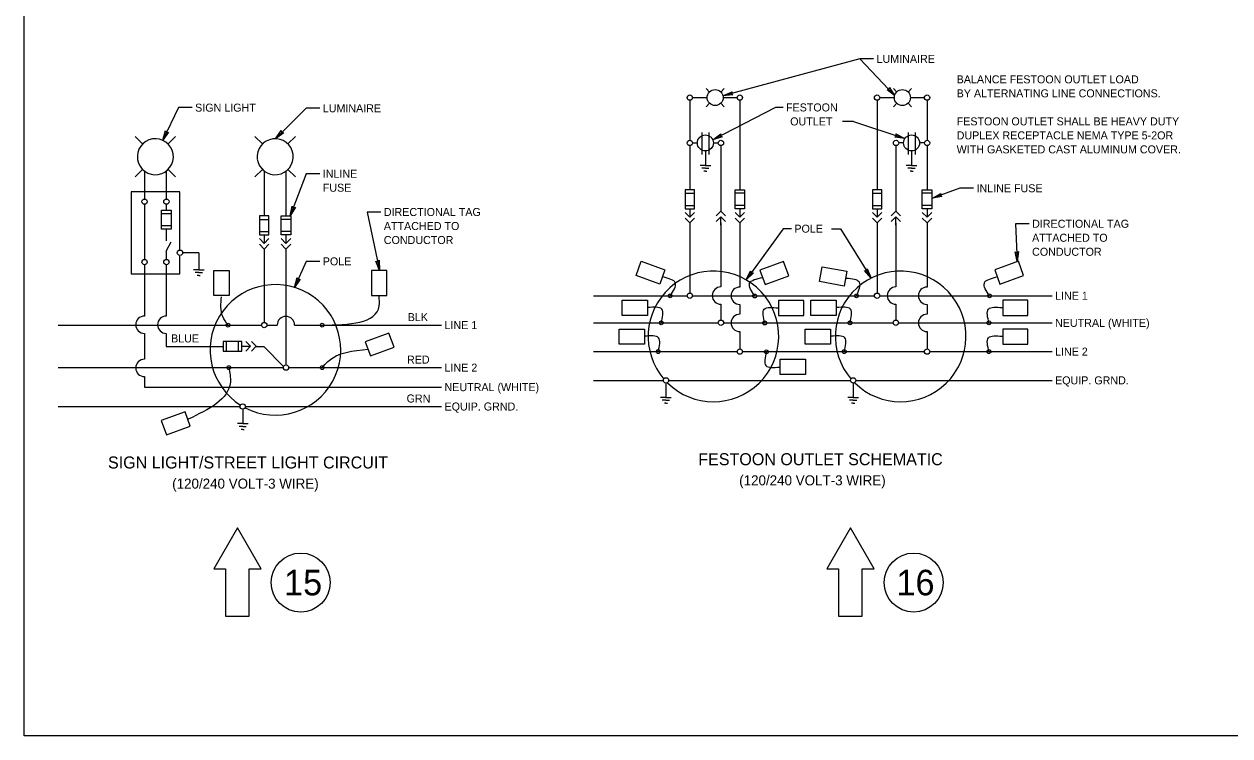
# Model space of a CAD drawing. Extents: x 99981 to 128681, y 99783 to 102182.
# Drawn here: x 120381 to 122189, y 99887 to 100954 of the extents above; entities that cross this region are included whole.
import ezdxf

# ---------------------------------------------------------------- set-up
doc = ezdxf.new("R2010")
doc.units = 0
for name, color, linetype in [('Default', 7, 'Continuous'), ('Level 1', 7, 'Continuous'), ('RD Lighting', 7, 'Continuous')]:
    doc.layers.add(name, color=color, linetype=linetype)

msp = doc.modelspace()

# ---------------------------------------------------------------- linework, layer by layer
at = {"layer": 'Default'}
msp.add_lwpolyline([(120381.4, 102086.3), (123581.1, 102086.3), (123581.1, 99886.7), (120381.4, 99886.7)], close=True, dxfattribs=at)
at = {"layer": 'Level 1'}
for p, q in [((121634.1, 100901.7), (121428.9, 100846.2)), ((121654.7, 100901.7), (121634.1, 100901.7)), ((121634.1, 100901.7), (121686.2, 100846.7)), ((121408.7, 100852), (121403.7, 100857.1)), ((121425.7, 100852), (121430.7, 100857.1)), ((121689.3, 100852), (121684.3, 100857.1)), ((121706.3, 100852), (121711.4, 100857.1)), ((121379.2, 100839.6), (121379.2, 100779.6)), ((121383.2, 100843.6), (121405.2, 100843.6)), ((121403.7, 100830), (121408.7, 100835.1)), ((121430.7, 100830), (121425.7, 100835.1)), ((121429.2, 100843.6), (121450.2, 100843.6)), ((121454.2, 100839.6), (121454.2, 100705.6)), ((121659.9, 100839.6), (121659.9, 100705.6)), ((121663.8, 100843.6), (121685.8, 100843.6)), ((121684.3, 100830), (121689.3, 100835.1)), ((121711.4, 100830), (121706.3, 100835.1)), ((121709.8, 100843.6), (121730.8, 100843.6)), ((121734.8, 100839.6), (121734.8, 100779.5)), ((120612.7, 100828.6), (120589.2, 100779.6)), ((120633.3, 100828.6), (120612.7, 100828.6)), ((120804.1, 100827.6), (120758.1, 100782)), ((120824.6, 100827.6), (120804.1, 100827.6)), ((121507.8, 100828.9), (121413.5, 100780.3)), ((121518.9, 100828.9), (121507.8, 100828.9)), ((121624.4, 100807.9), (121608.2, 100807.9)), ((121624.4, 100807.9), (121701.6, 100782.2)), ((120559, 100774.1), (120547.6, 100785.5)), ((120597.1, 100774.1), (120608.5, 100785.5)), ((120738.6, 100774.1), (120727.3, 100785.5)), ((120776.8, 100774.1), (120788.1, 100785.5)), ((121397.1, 100791.5), (121397.1, 100758.5)), ((121407.7, 100791.5), (121407.7, 100758.5)), ((121706.4, 100791.5), (121706.4, 100758.5)), ((121717.1, 100791.5), (121717.1, 100758.5)), ((121379.2, 100771.7), (121379.2, 100705.6)), ((121383.2, 100775.6), (121390.5, 100775.6)), ((121402.5, 100763.7), (121402.5, 100742)), ((121414.5, 100775.6), (121421.9, 100775.6)), ((121425.8, 100771.7), (121425.8, 100673.5)), ((121688, 100771.7), (121688, 100673.5)), ((121699.7, 100775.6), (121692.3, 100775.6)), ((121711.6, 100763.7), (121711.6, 100742)), ((121730.9, 100775.6), (121723.6, 100775.6)), ((121734.8, 100771.6), (121734.8, 100705.6)), ((121402.5, 100742), (121394.5, 100742)), ((121402.5, 100742), (121410.5, 100742)), ((121711.6, 100742), (121703.6, 100742)), ((121711.7, 100742), (121719.7, 100742)), ((120547.6, 100724.6), (120559, 100735.9)), ((120561.8, 100733.5), (120561.8, 100691.6)), ((120594.5, 100733.6), (120594.5, 100691.6)), ((120608.5, 100724.6), (120597.1, 100735.9)), ((120727.3, 100724.6), (120738.6, 100735.9)), ((120741.3, 100732.4), (120741.3, 100666.4)), ((120773.9, 100732.4), (120773.9, 100666.4)), ((120788.1, 100724.6), (120776.8, 100735.9)), ((120804.1, 100729.5), (120780.4, 100666.3)), ((120824.6, 100729.5), (120804.1, 100729.5)), ((121402.5, 100737.7), (121397.1, 100737.7)), ((121402.5, 100733.3), (121400.1, 100733.3)), ((121402.5, 100737.7), (121407.9, 100737.7)), ((121402.5, 100733.3), (121404.8, 100733.3)), ((121711.6, 100737.7), (121706.2, 100737.7)), ((121711.6, 100733.3), (121709.3, 100733.3)), ((121711.7, 100737.7), (121717.1, 100737.7)), ((121711.7, 100733.3), (121714, 100733.3)), ((121784, 100707.7), (121742.9, 100693.1)), ((121804.5, 100707.7), (121784, 100707.7)), ((121372.1, 100700.2), (121386.3, 100700.2)), ((121461.2, 100700.2), (121447.1, 100700.2)), ((121652.8, 100700.2), (121667, 100700.2)), ((121741.9, 100700.2), (121727.7, 100700.2)), ((120561.8, 100682.7), (120561.8, 100600.9)), ((120601.6, 100669.4), (120587.4, 100669.4)), ((120594.5, 100683.7), (120594.5, 100674.8)), ((120916.1, 100672.1), (120895.5, 100672.1)), ((120895.5, 100672.1), (120914.3, 100584.6)), ((121372.1, 100682.1), (121386.3, 100682.1)), ((121379.2, 100677.1), (121379.2, 100664.3)), ((121461.2, 100682.1), (121447.1, 100682.1)), ((121454.2, 100677.1), (121454.2, 100664.3)), ((121652.8, 100682.1), (121667, 100682.1)), ((121659.9, 100677.1), (121659.9, 100664.3)), ((121741.9, 100682.1), (121727.7, 100682.1)), ((121734.8, 100677.1), (121734.8, 100664.3)), ((120601.6, 100651.3), (120587.4, 100651.3)), ((120734.2, 100661), (120748.4, 100661)), ((120781, 100661), (120766.8, 100661)), ((121379.2, 100655.8), (121379.2, 100550.6)), ((121425.8, 100652.2), (121425.8, 100665)), ((121425.8, 100655.8), (121425.8, 100559.7)), ((121454.2, 100655.8), (121454.2, 100559.6)), ((121659.9, 100655.8), (121659.9, 100550.6)), ((121688, 100652.2), (121688, 100665)), ((121688, 100655.8), (121688, 100559.7)), ((121734.8, 100655.8), (121734.8, 100559.6)), ((121887.8, 100654.5), (121867.2, 100654.5)), ((121867.2, 100654.5), (121870.1, 100597.8)), ((120594.5, 100646.3), (120594.5, 100628.8)), ((120734.2, 100642.9), (120748.4, 100642.9)), ((120741.3, 100637.9), (120741.3, 100625.1)), ((120781, 100642.9), (120766.8, 100642.9)), ((120773.9, 100637.9), (120773.9, 100625.1)), ((121519, 100647.1), (121463.8, 100570.3)), ((121531.5, 100647.1), (121519, 100647.1)), ((121591.5, 100647.1), (121604.9, 100647.1)), ((121604.9, 100647.1), (121651, 100573)), ((120594.5, 100613.3), (120601.9, 100627.6)), ((120741.3, 100616.6), (120741.3, 100506.6)), ((120773.9, 100616.6), (120773.9, 100442.8)), ((120594.5, 100613.3), (120594.5, 100600.9)), ((120643.2, 100610.9), (120619, 100610.9)), ((120643.2, 100610.9), (120643.2, 100585.4)), ((120804.1, 100598.1), (120786.9, 100559)), ((120824.6, 100598.1), (120804.1, 100598.1)), ((120561.8, 100593), (120561.8, 100516)), ((120594.5, 100593), (120594.5, 100516)), ((120643.2, 100585.4), (120635.2, 100585.4)), ((120643.2, 100581.2), (120637.7, 100581.2)), ((120643.2, 100585.4), (120651.2, 100585.4)), ((120643.2, 100581.2), (120648.6, 100581.2)), ((120643.2, 100576.8), (120640.9, 100576.8)), ((120643.2, 100576.8), (120645.5, 100576.8)), ((121234.8, 100546.5), (121375.3, 100546.5)), ((121383.2, 100546.5), (121655.9, 100546.5)), ((121663.7, 100546.5), (121922.2, 100546.5)), ((121425.8, 100533.8), (121425.8, 100510)), ((121454.2, 100533.5), (121454.2, 100518.9)), ((121688, 100533.8), (121688, 100510)), ((121734.8, 100533.5), (121734.8, 100518.9)), ((120432.3, 100502.5), (120737.4, 100502.5)), ((120561.8, 100490), (120561.8, 100451.3)), ((120594.5, 100490.1), (120594.5, 100470.6)), ((120745.2, 100502.5), (120760.7, 100502.5)), ((120786.6, 100502.5), (121007.1, 100502.5)), ((121234.8, 100505.9), (121421.9, 100505.9)), ((121429.8, 100505.9), (121684.1, 100505.9)), ((121454.2, 100492.9), (121454.2, 100466.8)), ((121692.6, 100505.9), (121922.2, 100505.9)), ((121734.8, 100492.9), (121734.8, 100466.8)), ((120594.5, 100470.6), (120679.8, 100470.6)), ((120684.9, 100463.7), (120684.9, 100477.9)), ((120702.9, 100463.7), (120702.9, 100477.9)), ((120707.9, 100470.8), (120720.7, 100470.8)), ((120729.2, 100470.6), (120740.5, 100470.6)), ((120740.5, 100470.6), (120770.6, 100440.2)), ((121234.8, 100462.8), (121450.2, 100462.8)), ((121458.1, 100462.8), (121730.8, 100462.8)), ((121739.3, 100462.8), (121922.2, 100462.8)), ((120432.3, 100438.8), (120770, 100438.8)), ((120778.8, 100438.8), (121007.1, 100438.8)), ((120561.8, 100425.5), (120561.8, 100409.5)), ((121234.8, 100419.7), (121339.5, 100419.7)), ((121343.4, 100415.8), (121343.4, 100394.1)), ((121347.4, 100419.7), (121620.1, 100419.7)), ((121624.1, 100415.8), (121624.1, 100394.1)), ((121628.6, 100419.7), (121922.2, 100419.7)), ((120561.8, 100409.5), (121007.1, 100409.5)), ((120432.3, 100380.5), (120705, 100380.5)), ((120713.5, 100380.5), (121007.1, 100380.5)), ((121343.4, 100394.1), (121335.4, 100394.1)), ((121343.4, 100389.8), (121338, 100389.9)), ((121343.4, 100385.4), (121341.1, 100385.4)), ((121343.4, 100394.1), (121351.4, 100394.1)), ((121343.4, 100389.8), (121348.9, 100389.8)), ((121343.4, 100385.4), (121345.8, 100385.4)), ((121624, 100394.1), (121616.1, 100394.1)), ((121624, 100389.8), (121618.6, 100389.9)), ((121624, 100385.4), (121621.7, 100385.4)), ((121624.1, 100394.1), (121632.1, 100394.1)), ((121624.1, 100389.8), (121629.5, 100389.8)), ((121624.1, 100385.4), (121626.4, 100385.4)), ((120709, 100376.6), (120709, 100354.9)), ((120709, 100354.9), (120701, 100354.9)), ((120709, 100350.6), (120703.5, 100350.7)), ((120708.9, 100346.2), (120706.6, 100346.2)), ((120709, 100354.9), (120717, 100354.9)), ((120709, 100350.6), (120714.4, 100350.6)), ((120709, 100346.2), (120711.3, 100346.2))]:
    msp.add_line(p, q, dxfattribs=at)
for points in [[(121443.9, 100847.6), (121428.9, 100846.2), (121442.6, 100852.5), (121441, 100849.4)], [(121678.3, 100858.6), (121686.2, 100846.7), (121674.8, 100855.3), (121678, 100855.3)], [(120597.9, 100791.9), (120589.2, 100779.6), (120593.4, 100794.1), (120594.6, 100790.9)], [(120770.5, 100790.7), (120758.1, 100782), (120766.9, 100794.3), (120767, 100790.8)], [(121427.9, 100784.9), (121413.5, 100780.3), (121425.6, 100789.4), (121424.7, 100786.1)], [(121688.2, 100789.3), (121701.6, 100782.2), (121686.6, 100784.5), (121689.7, 100786.1)], [(121372.1, 100677.1), (121386.3, 100677.1), (121386.3, 100705.5), (121372.1, 100705.5)], [(121461.2, 100677.1), (121447.1, 100677.1), (121447.1, 100705.5), (121461.2, 100705.5)], [(121652.8, 100677.1), (121667, 100677.1), (121667, 100705.5), (121652.8, 100705.5)], [(121741.9, 100677.1), (121727.7, 100677.1), (121727.7, 100705.5), (121741.9, 100705.5)], [(121757, 100695.5), (121742.9, 100693.1), (121755.4, 100700.1), (121754.1, 100697.1)], [(120601.6, 100646.3), (120587.4, 100646.3), (120587.4, 100674.7), (120601.6, 100674.7)], [(120788, 100679.3), (120780.4, 100666.3), (120783.3, 100681.1), (120784.8, 100678)], [(120734.2, 100637.9), (120748.4, 100637.9), (120748.4, 100666.3), (120734.2, 100666.3)], [(120781, 100637.9), (120766.8, 100637.9), (120766.8, 100666.3), (120781, 100666.3)], [(120913.6, 100599.7), (120914.3, 100584.6), (120908.7, 100598.6), (120911.7, 100596.8)], [(121334.2, 100564.1), (121298.7, 100577), (121306.4, 100598.3), (121342, 100585.4)], [(121492, 100563.6), (121527.6, 100576.6), (121519.8, 100597.9), (121484.3, 100585)], [(121843.9, 100564.1), (121879.5, 100577), (121871.7, 100598.3), (121836.2, 100585.4)], [(121871.9, 100612.8), (121870.1, 100597.8), (121866.8, 100612.5), (121869.5, 100610.3)], [(120665.9, 100546.7), (120665.9, 100584.6), (120688.6, 100584.6), (120688.6, 100546.7)], [(120924.9, 100546.7), (120924.9, 100584.6), (120902.2, 100584.6), (120902.2, 100546.7)], [(121474.5, 100580.9), (121463.8, 100570.3), (121470.4, 100583.9), (121471.1, 100580.5)], [(121610.7, 100561.1), (121573.5, 100567.7), (121577.4, 100590.1), (121614.7, 100583.5)], [(121645.2, 100587), (121651, 100573), (121640.9, 100584.3), (121644.3, 100583.6)], [(120795.2, 100571.6), (120786.9, 100559), (120790.6, 100573.7), (120792, 100570.5)], [(121315.8, 100517.1), (121277.9, 100517.1), (121277.9, 100539.8), (121315.8, 100539.8)], [(121512.1, 100516.9), (121550, 100516.9), (121550, 100539.6), (121512.1, 100539.6)], [(121598.6, 100517.1), (121560.8, 100517.1), (121560.8, 100539.8), (121598.6, 100539.8)], [(121848.2, 100517.1), (121886, 100517.1), (121886, 100539.8), (121848.2, 100539.8)], [(120900.5, 100456.4), (120936, 100469.3), (120928.3, 100490.6), (120892.7, 100477.7)], [(121311.1, 100474), (121273.2, 100474), (121273.2, 100496.7), (121311.1, 100496.7)], [(121590.1, 100474), (121552.3, 100474), (121552.3, 100496.7), (121590.1, 100496.7)], [(121848.2, 100474), (121886, 100474), (121886, 100496.7), (121848.2, 100496.7)], [(120707.9, 100463.7), (120707.9, 100477.9), (120679.6, 100477.9), (120679.6, 100463.7)], [(121514.6, 100451.3), (121552.5, 100451.3), (121552.5, 100428.6), (121514.6, 100428.6)], [(120622.6, 100372.4), (120587, 100359.5), (120594.8, 100338.1), (120630.3, 100351.1)]]:
    msp.add_lwpolyline(points, close=True, dxfattribs=at)
for points in [[(120614.7, 100615.5), (120614.7, 100702.3), (120541.9, 100702.3), (120541.9, 100579.5), (120614.7, 100579.5), (120614.7, 100605.8)], [(121372.1, 100671.4), (121379.2, 100664.3), (121386.3, 100671.4)], [(121418.7, 100666.4), (121425.8, 100673.5), (121432.9, 100666.4)], [(121461.2, 100671.4), (121454.2, 100664.3), (121447.1, 100671.4)], [(121652.8, 100671.4), (121659.9, 100664.3), (121667, 100671.4)], [(121680.9, 100666.4), (121688, 100673.5), (121695.1, 100666.4)], [(121741.9, 100671.4), (121734.8, 100664.3), (121727.7, 100671.4)], [(121372.1, 100662.9), (121379.2, 100655.8), (121386.3, 100662.9)], [(121418.7, 100657.9), (121425.8, 100665), (121432.9, 100657.9)], [(121461.2, 100662.9), (121454.2, 100655.8), (121447.1, 100662.9)], [(121652.8, 100662.9), (121659.9, 100655.8), (121667, 100662.9)], [(121680.9, 100657.9), (121688, 100665), (121695.1, 100657.9)], [(121741.9, 100662.9), (121734.8, 100655.8), (121727.7, 100662.9)], [(120734.2, 100632.2), (120741.3, 100625.1), (120748.4, 100632.2)], [(120734.2, 100623.7), (120741.3, 100616.6), (120748.4, 100623.7)], [(120781, 100632.2), (120773.9, 100625.1), (120766.8, 100632.2)], [(120781, 100623.7), (120773.9, 100616.6), (120766.8, 100623.7)], [(120713.6, 100463.7), (120720.7, 100470.8), (120713.6, 100477.9)], [(120722.1, 100463.7), (120729.2, 100470.8), (120722.1, 100477.9)]]:
    msp.add_lwpolyline(points, dxfattribs=at)
for centre, radius in [((121417.2, 100843.6), 12), ((121697.8, 100843.6), 12), ((121379.2, 100843.6), 3.97), ((121454.2, 100843.6), 3.97), ((121659.9, 100843.6), 3.97), ((121734.8, 100843.6), 3.97), ((121379.2, 100775.6), 3.97), ((121402.5, 100775.6), 12), ((121425.8, 100775.6), 3.97), ((121688.3, 100775.6), 3.97), ((121711.6, 100775.6), 12), ((121734.9, 100775.6), 3.97), ((120561.9, 100687.6), 3.97), ((120594.7, 100687.6), 3.97), ((120615, 100611.1), 3.97), ((120561.9, 100597), 3.97), ((120594.7, 100597), 3.97), ((121349.8, 100546.5), 2.84), ((121379.2, 100546.6), 3.97), ((121476.5, 100546.1), 2.84), ((121629.1, 100546.5), 2.84), ((121659.9, 100546.6), 3.97), ((121828.4, 100546.5), 2.84), ((120741.3, 100502.6), 3.97), ((121336.4, 100505.9), 2.84), ((121425.8, 100506.1), 3.97), ((121491.5, 100505.7), 2.84), ((121619.3, 100505.9), 2.84), ((121688, 100506.1), 3.97), ((121827.6, 100505.9), 2.84), ((120687, 100502.5), 2.84), ((120828.2, 100502.5), 2.84), ((121331.7, 100462.8), 2.84), ((121454.2, 100462.8), 3.97), ((121494, 100462.5), 2.84), ((121610.7, 100462.8), 2.84), ((121734.8, 100462.8), 3.97), ((121827.6, 100462.8), 2.84), ((120688.3, 100438.8), 2.84), ((120773.9, 100438.8), 3.97), ((120828.2, 100438.8), 2.84), ((121343.5, 100419.7), 3.97), ((121624.1, 100419.7), 3.97), ((120709, 100380.5), 3.97)]:
    msp.add_circle(centre, radius, dxfattribs=at)
for centre, radius, start, end in [((120578.1, 100755), 27, 9.404, 8.9517), ((120757.7, 100755), 27, 187.5804, 187.2193), ((121414.6, 100485.6), 97.9, 225.4269, 220.7362), ((121695.2, 100485.6), 97.9, 225.4269, 220.7362), ((120758, 100465.4), 97.9, 242.5639, 237.8733), ((121425.9, 100546.7), 13, 90, 270), ((121454.1, 100546.6), 13, 90, 270), ((121688.1, 100546.7), 13, 90, 270), ((121734.8, 100546.6), 13, 90, 270), ((120561.7, 100503.1), 13, 90, 270), ((120594.5, 100503.1), 13, 90, 270), ((120773.7, 100502.6), 13, 360, 180), ((121454.1, 100505.9), 13, 90, 270), ((121734.8, 100505.9), 13, 90, 270), ((120561.7, 100438.3), 13, 90, 270)]:
    msp.add_arc(centre, radius, start, end, dxfattribs=at)
for points in [[(121349.8, 100546.5), (121357.5, 100565.6), (121339.2, 100574.8)], [(121476.5, 100546.1), (121468.8, 100565.2), (121488.2, 100574.1)], [(121629.1, 100546.5), (121633.4, 100566.7), (121613.8, 100572.6)], [(121828.4, 100546.5), (121820.7, 100565.6), (121839, 100574.8)], [(120687, 100502.5), (120679.1, 100515.2), (120677.1, 100545.1)], [(120828.2, 100502.5), (120913.5, 100531.4), (120913.5, 100546.2)], [(121336.4, 100505.9), (121337.1, 100526.6), (121316.8, 100528.9)], [(121491.5, 100505.7), (121490.8, 100526.4), (121511.9, 100528.3)], [(121619.3, 100505.9), (121619.9, 100526.6), (121599.6, 100528.9)], [(121827.6, 100505.9), (121826.9, 100526.6), (121847.2, 100528.9)], [(121331.7, 100462.8), (121332.4, 100483.5), (121312.1, 100485.8)], [(121610.7, 100462.8), (121611.4, 100483.5), (121591.1, 100485.8)], [(121827.6, 100462.8), (121826.9, 100483.5), (121847.2, 100485.8)], [(120828.2, 100438.8), (120836.4, 100447.8), (120897, 100466.5)], [(121494, 100462.5), (121493.3, 100441.9), (121513.6, 100439.5)], [(120688.3, 100438.8), (120690.5, 100416.8), (120627.4, 100361.5)]]:
    msp.add_spline(points, degree=3, dxfattribs=at)
at = {"layer": 'RD Lighting'}
for points in [[(120701.1, 100198.4), (120665.7, 100137), (120683.4, 100137), (120683.4, 100066), (120718.9, 100066), (120718.9, 100137), (120736.6, 100137)], [(121619.9, 100198.4), (121584.4, 100137), (121602.2, 100137), (121602.2, 100066), (121637.7, 100066), (121637.7, 100137), (121655.4, 100137)]]:
    msp.add_lwpolyline(points, close=True, dxfattribs=at)
for centre in [(120796, 100116.6), (121714.8, 100116.6)]:
    msp.add_circle(centre, 44.2, dxfattribs=at)

# ---------------------------------------------------------------- texts
at = {"layer": 'Level 1'}
for s, height, p in [(' LUMINAIRE', 12, (121654.7, 100895.7)), ('BALANCE FESTOON OUTLET LOAD', 12, (121779.2, 100865)), ('BY ALTERNATING LINE CONNECTIONS.', 12, (121779.2, 100844)), (' SIGN LIGHT', 12, (120633.3, 100822.6)), (' LUMINAIRE', 12, (120824.6, 100821.6)), (' FESTOON ', 12, (121518.9, 100822.9)), (' OUTLET ', 12, (121525.2, 100801.9)), ('FESTOON OUTLET SHALL BE HEAVY DUTY ', 12, (121779.2, 100802)), ('DUPLEX RECEPTACLE NEMA TYPE 5-2OR', 12, (121779.2, 100781)), ('WITH GASKETED CAST ALUMINUM COVER.', 12, (121779.2, 100760)), (' INLINE', 12, (120824.6, 100723.5)), (' FUSE', 12, (120824.6, 100702.5)), (' INLINE FUSE', 12, (121804.5, 100701.7)), (' DIRECTIONAL TAG', 12, (120916.1, 100666.1)), (' ATTACHED TO', 12, (120916.1, 100645.1)), (' POLE ', 12, (121531.5, 100641.1)), (' DIRECTIONAL TAG', 12, (121887.8, 100648.5)), (' CONDUCTOR', 12, (120916.1, 100624.1)), (' ATTACHED TO', 12, (121887.8, 100627.5)), (' CONDUCTOR', 12, (121887.8, 100606.5)), (' POLE', 12, (120824.6, 100592.1)), (' LINE 1', 12, (121922.2, 100540.5)), ('BLK', 12, (120956.4, 100508.5)), (' LINE 1', 12, (121007.1, 100496.5)), (' NEUTRAL (WHITE)', 12, (121922.2, 100499.9)), ('BLUE', 12, (120601.7, 100476.6)), ('RED', 12, (120955.3, 100444.8)), (' LINE 2', 12, (121922.2, 100456.8)), (' LINE 2', 12, (121007.1, 100432.8)), (' NEUTRAL (WHITE)', 12, (121007.1, 100403.5)), (' EQUIP. GRND.', 12, (121922.2, 100413.7)), ('GRN', 12, (120954.7, 100386.5)), (' EQUIP. GRND.', 12, (121007.1, 100374.5)), ('FESTOON OUTLET SCHEMATIC', 18, (121391.9, 100292.5)), ('SIGN LIGHT/STREET LIGHT CIRCUIT', 18, (120507.1, 100287.6)), ('(120/240 VOLT-3 WIRE)', 15, (120603.3, 100257.4)), ('(120/240 VOLT-3 WIRE)', 15, (121453.2, 100262.3))]:
    msp.add_text(s, height=height, dxfattribs=at).set_placement(p)
at = {"layer": 'RD Lighting'}
for s, p in [('15', (120771.1, 100097.4)), ('16', (121689, 100097.4))]:
    msp.add_text(s, height=38.31, dxfattribs=at).set_placement(p)

doc.saveas('drawing.dxf')
